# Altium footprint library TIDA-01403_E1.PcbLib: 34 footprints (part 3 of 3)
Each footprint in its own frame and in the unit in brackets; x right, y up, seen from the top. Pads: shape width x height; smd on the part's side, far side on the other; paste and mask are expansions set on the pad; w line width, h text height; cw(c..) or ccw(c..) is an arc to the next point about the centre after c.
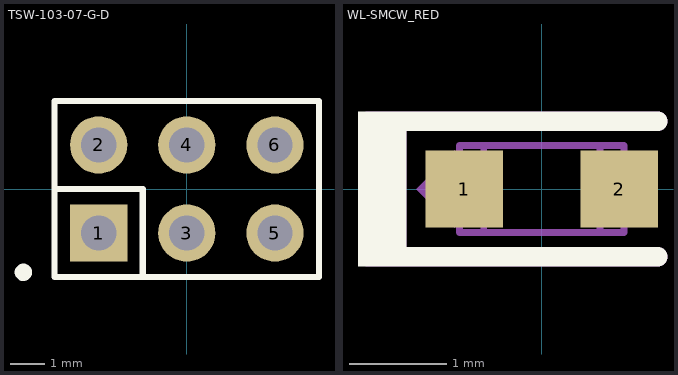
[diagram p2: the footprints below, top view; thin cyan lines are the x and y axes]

## TSW-103-07-G-D [mm] "Samtec 100mil, 2x3, 230 mil above insulator"
height 8.382
pads (6):
  rect 1.65x1.65 hole 1.016: 1(-2.54,-1.27)
  round 1.65 hole 1.016: 2(-2.54,1.27) 3(0,-1.27) 4(0,1.27) 5(2.54,-1.27) 6(2.54,1.27)
Top Overlay:
  circle w0.25: c-4.71,-2.4 r0.125
  lines w0.178: -3.81,0 -1.27,0 -1.27,-2.54 ; -3.81,-2.54 -3.81,2.54 3.81,2.54 3.81,-2.54 -3.81,-2.54
Mechanical 5:
  rectangle: -3.048,-1.778 -2.032,-0.762
  lines w0.127: -3.81,-2.54 3.81,-2.54 3.81,2.54 -3.81,2.54 -3.81,-2.54
  text ".Designator" at -0.406,-0.203 h0.64
3D body: height 8.38, standoff -2.54, extent -3.81,-2.54 3.81,2.54

## WL-SMCW_RED [mm] "WURTH"
height 0.8
pads (2):
  rect 0.8x0.8 smd: 1(-0.8,0) 2(0.8,0)
Top Overlay:
  rectangle: -1.9,-0.8 -1.4,0.8
  lines w0.2: -1.6,-0.7 1.2,-0.7 ; -1.6,0.7 1.2,0.7
Mechanical 5:
  region: -0.9,-0.4 -0.9,0.4 -1.3,0
  lines w0.2: -1.65,-0.7 -1.65,0.55 ; 1.2,-0.7 -1.5,-0.7 ; 1.2,0.7 -1.5,0.7 ; -1.5,-0.7 -1.5,0.7 ; -1.5,-0.7 -1.8,-0.7 -1.8,0.7 -1.5,0.7
  text ".Designator" at 0.743,0.305 h0.64
Mechanical 13:
  lines w0.07: -0.6,-0.45 -0.6,0.45 ; 0.6,-0.45 0.6,0.45 ; -0.85,-0.45 -0.85,0.45 0.85,0.45 0.85,-0.45 -0.85,-0.45
3D body: height 0.35, standoff 0, extent -0.849,-0.449 -0.601,0.449
3D body: height 0.35, standoff 0, extent -0.599,-0.449 0.599,0.449
3D body: height 0.35, standoff 0, extent 0.601,-0.449 0.849,0.449
3D body: height 0.8, standoff 0.35, extent -0.599,-0.449 0.599,0.449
